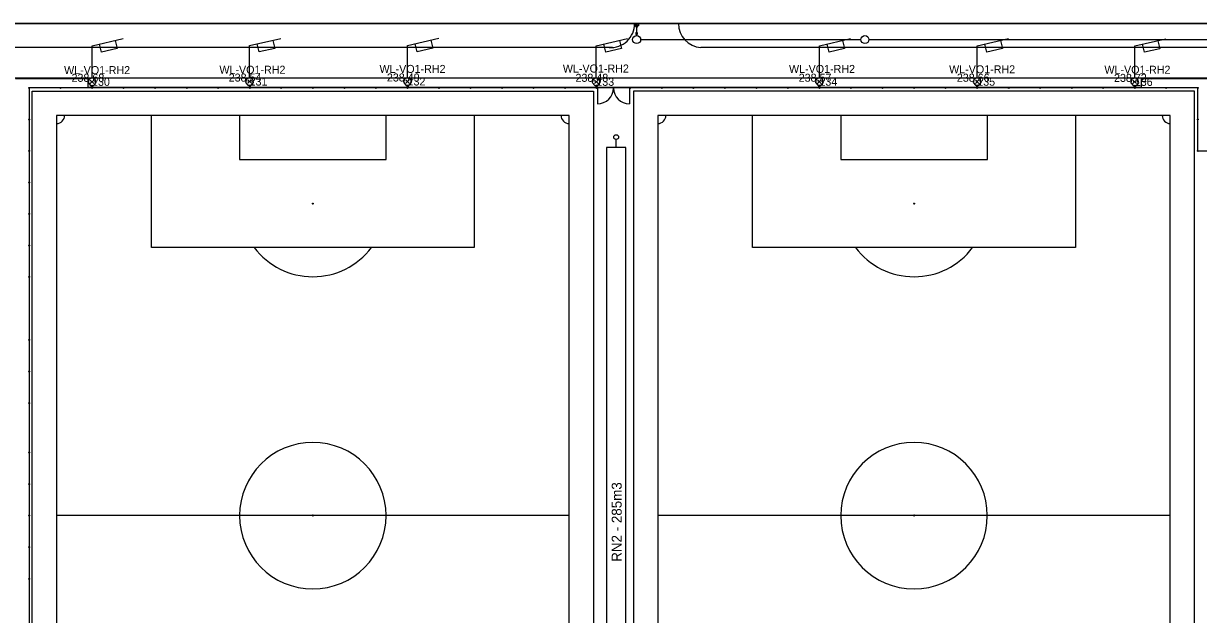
# Model space of a CAD drawing. Extents: x -264222 to -263592, y -1242345 to -1242048.
# Drawn here: x -264118.8 to -263972, y -1242253.3 to -1242179.5 of the extents above; entities that cross this region are included whole.
import ezdxf

# ---------------------------------------------------------------- set-up
doc = ezdxf.new("R2010")
doc.units = 0
for name, color, linetype in [('BOD_CISLO', 7, 'Continuous'), ('BOD_SYMBOL', 7, 'Continuous'), ('BOD_VYSKA', 7, 'Continuous'), ('KFA_2D_SITUACIA_DSP', 7, 'Continuous'), ('KFA_SO_62-1_VO_LAMPY_MERANE', 7, 'Continuous'), ('KFA_SO_62-1_VO_POPIS_LAMP_PROJEKT', 7, 'Continuous'), ('KFA_SO_62-1_VO_TRASA_KABLOV_PROJEKT', 7, 'Continuous')]:
    doc.layers.add(name, color=color, linetype=linetype)

msp = doc.modelspace()

# ---------------------------------------------------------------- linework, layer by layer
at = {"layer": 'BOD_SYMBOL'}
for p, q in [((-264110.42, -1242186.99), (-264109.98, -1242186.55)), ((-264109.98, -1242186.99), (-264110.42, -1242186.55)), ((-264090.74, -1242186.96), (-264090.3, -1242186.52)), ((-264090.3, -1242186.96), (-264090.74, -1242186.52)), ((-264071.01, -1242186.95), (-264070.57, -1242186.51)), ((-264070.57, -1242186.95), (-264071.01, -1242186.51)), ((-264047.43, -1242186.99), (-264046.98, -1242186.55)), ((-264046.98, -1242186.99), (-264047.43, -1242186.55)), ((-264019.56, -1242186.98), (-264019.12, -1242186.53)), ((-264019.12, -1242186.98), (-264019.56, -1242186.53)), ((-263999.85, -1242186.98), (-263999.41, -1242186.54)), ((-263999.41, -1242186.98), (-263999.85, -1242186.54)), ((-263980.17, -1242187), (-263979.72, -1242186.56)), ((-263979.72, -1242187), (-263980.17, -1242186.56))]:
    msp.add_line(p, q, dxfattribs=at)
at = {"layer": 'KFA_2D_SITUACIA_DSP'}
for p, q in [((-264077.23, -1242179.48), (-264131.57, -1242179.48)), ((-264131.57, -1242179.48), (-263959.47, -1242179.48)), ((-263959.47, -1242179.48), (-264131.57, -1242179.48)), ((-263959.47, -1242179.48), (-264077.23, -1242179.48)), ((-264042.42, -1242179.48), (-264041.92, -1242179.48)), ((-264042.42, -1242179.77), (-264042.42, -1242179.48)), ((-264042.42, -1242179.48), (-264041.92, -1242179.77)), ((-264042.42, -1242179.48), (-264041.92, -1242179.77)), ((-264041.92, -1242179.48), (-264042.42, -1242179.48)), ((-264041.92, -1242179.77), (-264042.42, -1242179.77)), ((-264042.17, -1242179.97), (-264042.17, -1242181)), ((-264041.92, -1242179.48), (-264041.92, -1242179.77)), ((-264041.92, -1242179.77), (-264041.92, -1242179.48)), ((-264041.67, -1242181.5), (-264014.16, -1242181.5)), ((-264013.16, -1242181.5), (-263964.16, -1242181.5)), ((-264045.2, -1242182.48), (-264131.57, -1242182.48)), ((-263960.12, -1242182.48), (-264034.16, -1242182.48)), ((-264118.01, -1242187.53), (-264118.13, -1242187.53)), ((-264118.07, -1242187.59), (-264118.07, -1242187.47)), ((-263972.07, -1242187.53), (-264118.07, -1242187.53)), ((-264118.07, -1242187.53), (-264118.07, -1242294.43)), ((-264114.07, -1242187.53), (-264114.19, -1242187.53)), ((-264114.13, -1242187.59), (-264114.13, -1242187.47)), ((-264110.13, -1242187.53), (-264110.25, -1242187.53)), ((-264110.19, -1242187.59), (-264110.19, -1242187.47)), ((-264106.19, -1242187.53), (-264106.31, -1242187.53)), ((-264106.25, -1242187.59), (-264106.25, -1242187.47)), ((-264102.25, -1242187.53), (-264102.37, -1242187.53)), ((-264102.31, -1242187.59), (-264102.31, -1242187.47)), ((-264098.31, -1242187.53), (-264098.43, -1242187.53)), ((-264098.37, -1242187.59), (-264098.37, -1242187.47)), ((-264094.37, -1242187.53), (-264094.49, -1242187.53)), ((-264094.43, -1242187.59), (-264094.43, -1242187.47)), ((-264090.44, -1242187.53), (-264090.56, -1242187.53)), ((-264090.5, -1242187.59), (-264090.5, -1242187.47)), ((-264086.5, -1242187.53), (-264086.62, -1242187.53)), ((-264086.56, -1242187.59), (-264086.56, -1242187.47)), ((-264082.56, -1242187.53), (-264082.68, -1242187.53)), ((-264082.62, -1242187.59), (-264082.62, -1242187.47)), ((-264078.62, -1242187.53), (-264078.74, -1242187.53)), ((-264078.68, -1242187.59), (-264078.68, -1242187.47)), ((-264074.68, -1242187.53), (-264074.8, -1242187.53)), ((-264074.74, -1242187.59), (-264074.74, -1242187.47)), ((-264070.74, -1242187.53), (-264070.86, -1242187.53)), ((-264070.8, -1242187.59), (-264070.8, -1242187.47)), ((-264066.8, -1242187.53), (-264066.92, -1242187.53)), ((-264066.86, -1242187.59), (-264066.86, -1242187.47)), ((-264062.86, -1242187.53), (-264062.98, -1242187.53)), ((-264062.92, -1242187.59), (-264062.92, -1242187.47)), ((-264058.92, -1242187.53), (-264059.04, -1242187.53)), ((-264058.98, -1242187.59), (-264058.98, -1242187.47)), ((-264054.99, -1242187.53), (-264055.11, -1242187.53)), ((-264055.05, -1242187.59), (-264055.05, -1242187.47)), ((-264051.05, -1242187.53), (-264051.17, -1242187.53)), ((-264051.11, -1242187.59), (-264051.11, -1242187.47)), ((-264047.11, -1242187.53), (-264047.23, -1242187.53)), ((-264047.17, -1242187.59), (-264047.17, -1242187.47)), ((-264047.07, -1242187.53), (-264047.07, -1242189.53)), ((-264044.57, -1242187.53), (-264045.57, -1242187.53)), ((-264043.07, -1242187.53), (-264043.07, -1242189.53)), ((-264042.91, -1242187.53), (-264043.03, -1242187.53)), ((-264042.97, -1242187.59), (-264042.97, -1242187.47)), ((-264039.09, -1242187.53), (-264038.97, -1242187.53)), ((-264039.03, -1242187.59), (-264039.03, -1242187.47)), ((-264035.15, -1242187.53), (-264035.03, -1242187.53)), ((-264035.09, -1242187.59), (-264035.09, -1242187.47)), ((-264031.21, -1242187.53), (-264031.09, -1242187.53)), ((-264031.15, -1242187.59), (-264031.15, -1242187.47)), ((-264027.27, -1242187.53), (-264027.15, -1242187.53)), ((-264027.21, -1242187.59), (-264027.21, -1242187.47)), ((-264023.33, -1242187.53), (-264023.21, -1242187.53)), ((-264023.27, -1242187.59), (-264023.27, -1242187.47)), ((-264019.39, -1242187.53), (-264019.27, -1242187.53)), ((-264019.33, -1242187.59), (-264019.33, -1242187.47)), ((-264015.46, -1242187.53), (-264015.34, -1242187.53)), ((-264015.4, -1242187.59), (-264015.4, -1242187.47)), ((-264011.52, -1242187.53), (-264011.4, -1242187.53)), ((-264011.46, -1242187.59), (-264011.46, -1242187.47)), ((-264007.58, -1242187.53), (-264007.46, -1242187.53)), ((-264007.52, -1242187.59), (-264007.52, -1242187.47)), ((-264003.64, -1242187.53), (-264003.52, -1242187.53)), ((-264003.58, -1242187.59), (-264003.58, -1242187.47)), ((-263999.7, -1242187.53), (-263999.58, -1242187.53)), ((-263999.64, -1242187.59), (-263999.64, -1242187.47)), ((-263995.76, -1242187.53), (-263995.64, -1242187.53)), ((-263995.7, -1242187.59), (-263995.7, -1242187.47)), ((-263991.82, -1242187.53), (-263991.7, -1242187.53)), ((-263991.76, -1242187.59), (-263991.76, -1242187.47)), ((-263987.88, -1242187.53), (-263987.76, -1242187.53)), ((-263987.82, -1242187.59), (-263987.82, -1242187.47)), ((-263983.94, -1242187.53), (-263983.82, -1242187.53)), ((-263983.88, -1242187.59), (-263983.88, -1242187.47)), ((-263980.01, -1242187.53), (-263979.89, -1242187.53)), ((-263979.95, -1242187.59), (-263979.95, -1242187.47)), ((-263976.07, -1242187.53), (-263975.95, -1242187.53)), ((-263976.01, -1242187.59), (-263976.01, -1242187.47)), ((-263972.13, -1242187.53), (-263972.01, -1242187.53)), ((-263972.07, -1242187.59), (-263972.07, -1242187.47)), ((-263972.07, -1242195.41), (-263972.07, -1242187.53)), ((-264118.01, -1242191.47), (-264118.13, -1242191.47)), ((-264118.07, -1242191.41), (-264118.07, -1242191.53)), ((-264050.62, -1242190.98), (-264114.62, -1242190.98)), ((-264114.62, -1242190.98), (-264114.62, -1242290.98)), ((-264102.78, -1242207.48), (-264102.78, -1242190.98)), ((-264091.78, -1242190.98), (-264091.78, -1242196.48)), ((-264073.46, -1242196.48), (-264073.46, -1242190.98)), ((-264062.46, -1242190.98), (-264062.46, -1242207.48)), ((-264050.62, -1242290.98), (-264050.62, -1242190.98)), ((-263975.52, -1242190.98), (-264039.52, -1242190.98)), ((-264039.52, -1242190.98), (-264039.52, -1242290.98)), ((-264027.68, -1242207.48), (-264027.68, -1242190.98)), ((-264016.68, -1242190.98), (-264016.68, -1242196.48)), ((-263998.36, -1242196.48), (-263998.36, -1242190.98)), ((-263987.36, -1242190.98), (-263987.36, -1242207.48)), ((-263975.52, -1242290.98), (-263975.52, -1242190.98)), ((-263972.13, -1242191.47), (-263972.01, -1242191.47)), ((-263972.07, -1242191.41), (-263972.07, -1242191.53)), ((-264044.73, -1242194.98), (-264044.73, -1242193.98)), ((-264118.01, -1242195.41), (-264118.13, -1242195.41)), ((-264118.07, -1242195.35), (-264118.07, -1242195.47)), ((-264043.53, -1242194.98), (-264045.93, -1242194.98)), ((-264045.93, -1242194.98), (-264045.93, -1242293.98)), ((-264043.53, -1242293.98), (-264043.53, -1242194.98)), ((-263972.07, -1242195.41), (-263967.42, -1242195.41)), ((-264091.78, -1242196.48), (-264073.46, -1242196.48)), ((-264016.68, -1242196.48), (-263998.36, -1242196.48)), ((-264118.07, -1242199.28), (-264118.07, -1242199.4)), ((-264118.01, -1242199.34), (-264118.13, -1242199.34)), ((-264118.01, -1242203.28), (-264118.13, -1242203.28)), ((-264118.07, -1242203.22), (-264118.07, -1242203.34)), ((-264118.01, -1242207.22), (-264118.13, -1242207.22)), ((-264118.07, -1242207.16), (-264118.07, -1242207.28)), ((-264062.46, -1242207.48), (-264102.78, -1242207.48)), ((-263987.36, -1242207.48), (-264027.68, -1242207.48)), ((-264118.01, -1242211.16), (-264118.13, -1242211.16)), ((-264118.07, -1242211.1), (-264118.07, -1242211.22)), ((-264118.01, -1242219.03), (-264118.13, -1242219.03)), ((-264118.07, -1242218.97), (-264118.07, -1242219.09)), ((-264118.01, -1242222.97), (-264118.13, -1242222.97)), ((-264118.07, -1242222.91), (-264118.07, -1242223.03)), ((-264118.01, -1242226.91), (-264118.13, -1242226.91)), ((-264118.07, -1242226.85), (-264118.07, -1242226.97)), ((-264118.07, -1242233.05), (-264118.07, -1242233.17)), ((-264118.01, -1242233.11), (-264118.13, -1242233.11)), ((-264118.01, -1242237.04), (-264118.13, -1242237.04)), ((-264118.07, -1242236.98), (-264118.07, -1242237.1)), ((-264118.01, -1242240.98), (-264118.13, -1242240.98)), ((-264118.07, -1242241.04), (-264118.07, -1242240.92)), ((-264050.62, -1242240.98), (-264114.62, -1242240.98)), ((-263975.52, -1242240.98), (-264039.52, -1242240.98)), ((-264118.01, -1242244.92), (-264118.13, -1242244.92)), ((-264118.07, -1242244.98), (-264118.07, -1242244.86)), ((-264118.01, -1242248.86), (-264118.13, -1242248.86)), ((-264118.07, -1242248.92), (-264118.07, -1242248.8))]:
    msp.add_line(p, q, dxfattribs=at)
for points in [[(-264117.67, -1242187.93), (-264047.57, -1242187.93), (-264047.57, -1242294.03), (-264117.67, -1242294.03)], [(-264042.57, -1242294.03), (-263972.47, -1242294.03), (-263972.47, -1242187.93), (-264042.57, -1242187.93)]]:
    msp.add_lwpolyline(points, close=True, dxfattribs=at)
for centre, radius in [((-264042.17, -1242179.87), 0.1), ((-264042.17, -1242181.5), 0.5), ((-264013.66, -1242181.5), 0.5), ((-264118.07, -1242187.53), 0.06), ((-264114.13, -1242187.53), 0.06), ((-264110.19, -1242187.53), 0.06), ((-264106.25, -1242187.53), 0.06), ((-264102.31, -1242187.53), 0.06), ((-264098.37, -1242187.53), 0.06), ((-264094.43, -1242187.53), 0.06), ((-264090.5, -1242187.53), 0.06), ((-264086.56, -1242187.53), 0.06), ((-264082.62, -1242187.53), 0.06), ((-264078.68, -1242187.53), 0.06), ((-264074.74, -1242187.53), 0.06), ((-264070.8, -1242187.53), 0.06), ((-264066.86, -1242187.53), 0.06), ((-264062.92, -1242187.53), 0.06), ((-264058.98, -1242187.53), 0.06), ((-264055.05, -1242187.53), 0.06), ((-264051.11, -1242187.53), 0.06), ((-264047.17, -1242187.53), 0.06), ((-264042.97, -1242187.53), 0.06), ((-264039.03, -1242187.53), 0.06), ((-264035.09, -1242187.53), 0.06), ((-264031.15, -1242187.53), 0.06), ((-264027.21, -1242187.53), 0.06), ((-264023.27, -1242187.53), 0.06), ((-264019.33, -1242187.53), 0.06), ((-264015.4, -1242187.53), 0.06), ((-264011.46, -1242187.53), 0.06), ((-264007.52, -1242187.53), 0.06), ((-264003.58, -1242187.53), 0.06), ((-263999.64, -1242187.53), 0.06), ((-263995.7, -1242187.53), 0.06), ((-263991.76, -1242187.53), 0.06), ((-263987.82, -1242187.53), 0.06), ((-263983.88, -1242187.53), 0.06), ((-263979.95, -1242187.53), 0.06), ((-263976.01, -1242187.53), 0.06), ((-263972.07, -1242187.53), 0.06), ((-264118.07, -1242191.47), 0.06), ((-263972.07, -1242191.47), 0.06), ((-264044.73, -1242193.68), 0.3), ((-264118.07, -1242195.41), 0.06), ((-263972.07, -1242195.41), 0.06), ((-264118.07, -1242199.34), 0.06), ((-264082.62, -1242201.98), 0.06), ((-264007.52, -1242201.98), 0.06), ((-264118.07, -1242203.28), 0.06), ((-264118.07, -1242207.22), 0.06), ((-264118.07, -1242211.16), 0.06), ((-264118.07, -1242219.03), 0.06), ((-264118.07, -1242222.97), 0.06), ((-264118.07, -1242226.91), 0.06), ((-264118.07, -1242233.11), 0.06), ((-264118.07, -1242237.04), 0.06), ((-264118.07, -1242240.98), 0.06), ((-264118.07, -1242244.92), 0.06), ((-264118.07, -1242248.86), 0.06)]:
    msp.add_circle(centre, radius, dxfattribs=at)
for centre, radius, start, end in [((-264045.41, -1242179.5), 2.99, 266.0314, 0.25), ((-264033.95, -1242179.5), 2.99, 179.75, 266.0314), ((-264042.17, -1242180.74), 0.125, 0, 180), ((-264042.17, -1242180.74), 0.125, 180, 0), ((-264047.07, -1242187.53), 2, 270, 360), ((-264043.07, -1242187.53), 2, 180, 270), ((-264114.62, -1242190.98), 1, 270, 360), ((-264050.62, -1242190.98), 1, 180, 270), ((-264039.52, -1242190.98), 1, 270, 360), ((-263975.52, -1242190.98), 1, 180, 270), ((-264082.62, -1242201.98), 0.0303, 90, 270), ((-264082.62, -1242201.98), 0.0303, 270, 90), ((-264007.52, -1242201.98), 0.0303, 90, 270), ((-264007.52, -1242201.98), 0.0303, 270, 90), ((-264082.62, -1242201.98), 9.15, 216.9482, 323.0518), ((-264007.52, -1242201.98), 9.15, 216.9482, 323.0518), ((-264082.62, -1242240.98), 9.15, 360, 180), ((-264007.52, -1242240.98), 9.15, 360, 180), ((-264082.62, -1242240.98), 9.15, 180, 360), ((-264082.62, -1242240.98), 0.0605, 90, 270), ((-264082.62, -1242240.98), 0.0605, 270, 90), ((-264007.52, -1242240.98), 9.15, 180, 360), ((-264007.52, -1242240.98), 0.0605, 90, 270), ((-264007.52, -1242240.98), 0.0605, 270, 90)]:
    msp.add_arc(centre, radius, start, end, dxfattribs=at)
at = {"layer": 'KFA_SO_62-1_VO_LAMPY_MERANE'}
for p, q in [((-264110.25, -1242186.77), (-264110.15, -1242186.77)), ((-264110.2, -1242186.77), (-264110.2, -1242186.77)), ((-264090.57, -1242186.74), (-264090.47, -1242186.74)), ((-264090.52, -1242186.74), (-264090.52, -1242186.74)), ((-264070.84, -1242186.73), (-264070.74, -1242186.73)), ((-264070.79, -1242186.73), (-264070.79, -1242186.73)), ((-264047.26, -1242186.77), (-264047.16, -1242186.77)), ((-264047.21, -1242186.77), (-264047.21, -1242186.77)), ((-264019.39, -1242186.76), (-264019.29, -1242186.76)), ((-264019.34, -1242186.76), (-264019.34, -1242186.76)), ((-263999.68, -1242186.76), (-263999.58, -1242186.76)), ((-263999.63, -1242186.76), (-263999.63, -1242186.76)), ((-263980, -1242186.78), (-263979.9, -1242186.78)), ((-263979.95, -1242186.78), (-263979.95, -1242186.78))]:
    msp.add_line(p, q, dxfattribs=at)
for points in [[(-264110.2, -1242186.27), (-264110.6, -1242186.47), (-264110.7, -1242186.87), (-264110.4, -1242187.22), (-264110, -1242187.22), (-264109.7, -1242186.87), (-264109.8, -1242186.47), (-264110.2, -1242186.27), (-264110.2, -1242182.27), (-264106.3, -1242181.37)], [(-264107.3, -1242181.62), (-264107.05, -1242182.62), (-264109, -1242183.07), (-264109.25, -1242182.07)], [(-264090.52, -1242186.24), (-264090.92, -1242186.44), (-264091.02, -1242186.84), (-264090.72, -1242187.19), (-264090.32, -1242187.19), (-264090.02, -1242186.84), (-264090.12, -1242186.44), (-264090.52, -1242186.24), (-264090.52, -1242182.24), (-264086.62, -1242181.34)], [(-264087.62, -1242181.59), (-264087.37, -1242182.59), (-264089.32, -1242183.04), (-264089.57, -1242182.04)], [(-264070.79, -1242186.23), (-264071.19, -1242186.43), (-264071.29, -1242186.83), (-264070.99, -1242187.18), (-264070.59, -1242187.18), (-264070.29, -1242186.83), (-264070.39, -1242186.43), (-264070.79, -1242186.23), (-264070.79, -1242182.23), (-264066.89, -1242181.33)], [(-264067.89, -1242181.58), (-264067.64, -1242182.58), (-264069.59, -1242183.03), (-264069.84, -1242182.03)], [(-264047.21, -1242186.27), (-264047.6, -1242186.47), (-264047.71, -1242186.87), (-264047.41, -1242187.22), (-264047.01, -1242187.22), (-264046.71, -1242186.87), (-264046.8, -1242186.47), (-264047.21, -1242186.27), (-264047.21, -1242182.27), (-264043.3, -1242181.37)], [(-264044.3, -1242181.62), (-264044.05, -1242182.62), (-264046.01, -1242183.07), (-264046.26, -1242182.07)], [(-264019.34, -1242186.26), (-264019.74, -1242186.46), (-264019.84, -1242186.85), (-264019.54, -1242187.21), (-264019.14, -1242187.21), (-264018.84, -1242186.85), (-264018.94, -1242186.46), (-264019.34, -1242186.26), (-264019.34, -1242182.26), (-264015.44, -1242181.35)], [(-264016.44, -1242181.6), (-264016.19, -1242182.6), (-264018.14, -1242183.05), (-264018.39, -1242182.05)], [(-263999.63, -1242186.26), (-264000.03, -1242186.46), (-264000.13, -1242186.86), (-263999.83, -1242187.21), (-263999.43, -1242187.21), (-263999.13, -1242186.86), (-263999.23, -1242186.46), (-263999.63, -1242186.26), (-263999.63, -1242182.26), (-263995.73, -1242181.36)], [(-263996.73, -1242181.61), (-263996.48, -1242182.61), (-263998.43, -1242183.06), (-263998.68, -1242182.06)], [(-263979.95, -1242186.28), (-263980.35, -1242186.48), (-263980.45, -1242186.88), (-263980.15, -1242187.23), (-263979.75, -1242187.23), (-263979.45, -1242186.88), (-263979.55, -1242186.48), (-263979.95, -1242186.28), (-263979.95, -1242182.28), (-263976.05, -1242181.38)], [(-263977.05, -1242181.63), (-263976.8, -1242182.63), (-263978.75, -1242183.08), (-263979, -1242182.08)]]:
    msp.add_lwpolyline(points, dxfattribs=at)
at = {"layer": 'KFA_SO_62-1_VO_TRASA_KABLOV_PROJEKT'}
for p, q in [((-263948.69, -1242186.3), (-264119.79, -1242186.3)), ((-264119.74, -1242186.35), (-264110.74, -1242186.35)), ((-264110.74, -1242186.35), (-264110.74, -1242187.45)), ((-264110.74, -1242187.45), (-264110.29, -1242187.45)), ((-264110.29, -1242187.45), (-264110.19, -1242187.15)), ((-264110.19, -1242187.15), (-264110.09, -1242187.45)), ((-264110.09, -1242187.45), (-264090.59, -1242187.45)), ((-264090.59, -1242187.45), (-264090.49, -1242187.15)), ((-264090.49, -1242187.15), (-264090.39, -1242187.45)), ((-264090.39, -1242187.45), (-264070.89, -1242187.45)), ((-264070.89, -1242187.45), (-264070.79, -1242187.15)), ((-264070.79, -1242187.15), (-264070.69, -1242187.45)), ((-264070.69, -1242187.45), (-264047.24, -1242187.45)), ((-264047.24, -1242187.45), (-264047.17, -1242187.15)), ((-264047.17, -1242187.15), (-264047.09, -1242187.45)), ((-264047.09, -1242187.45), (-264019.44, -1242187.45)), ((-264019.44, -1242187.45), (-264019.34, -1242187.15)), ((-264019.34, -1242187.15), (-264019.24, -1242187.45)), ((-264019.24, -1242187.45), (-263999.69, -1242187.45)), ((-263999.69, -1242187.45), (-263999.64, -1242187.15)), ((-263999.64, -1242187.15), (-263999.54, -1242187.45)), ((-263999.54, -1242187.45), (-263980.04, -1242187.45)), ((-263980.04, -1242187.45), (-263979.94, -1242187.15)), ((-263979.94, -1242187.15), (-263979.84, -1242187.45)), ((-263979.84, -1242187.45), (-263979.09, -1242187.45)), ((-263979.09, -1242187.45), (-263979.09, -1242186.35)), ((-263979.09, -1242186.35), (-263948.74, -1242186.35))]:
    msp.add_line(p, q, dxfattribs=at)

# ---------------------------------------------------------------- texts
at = {"layer": 'BOD_CISLO'}
for s, p in [('130', (-264110.2, -1242187.27)), ('131', (-264090.52, -1242187.24)), ('132', (-264070.79, -1242187.23)), ('133', (-264047.21, -1242187.27)), ('134', (-264019.34, -1242187.26)), ('135', (-263999.63, -1242187.26)), ('136', (-263979.95, -1242187.28))]:
    msp.add_text(s, height=1, dxfattribs=at).set_placement(p)
at = {"layer": 'BOD_VYSKA'}
for s, p in [('238.68', (-264112.76, -1242186.77)), ('238.54', (-264093.13, -1242186.74)), ('238.49', (-264073.37, -1242186.73)), ('238.48', (-264049.81, -1242186.77)), ('238.57', (-264021.93, -1242186.76)), ('238.66', (-264002.17, -1242186.76)), ('238.72', (-263982.54, -1242186.78))]:
    msp.add_text(s, height=1, dxfattribs=at).set_placement(p)
at = {"layer": 'KFA_2D_SITUACIA_DSP'}
msp.add_text('RN2 - 285m3', height=1.25, rotation=90, dxfattribs=at).set_placement((-264044.04, -1242246.75))
at = {"layer": 'KFA_SO_62-1_VO_POPIS_LAMP_PROJEKT'}
for p in [(-264051.39, -1242185.61), (-264113.69, -1242185.81), (-264094.29, -1242185.76), (-264074.29, -1242185.66), (-264023.14, -1242185.66), (-264003.14, -1242185.71), (-263983.74, -1242185.76)]:
    msp.add_text('WL-VO1-RH2', height=1, dxfattribs=at).set_placement(p)

doc.saveas('drawing.dxf')
